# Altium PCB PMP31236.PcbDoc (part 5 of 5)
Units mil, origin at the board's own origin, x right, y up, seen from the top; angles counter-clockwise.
Board outline 6425 x 5322.16 mil, 6 copper layers (Top Layer, Power / GND 1, Signal Layer 1, Signal Layer 2, Power / GND 2, Bottom Layer), stack 78.712 mil thick; 732 components, 346 nets, 1735 pads, 719 vias.
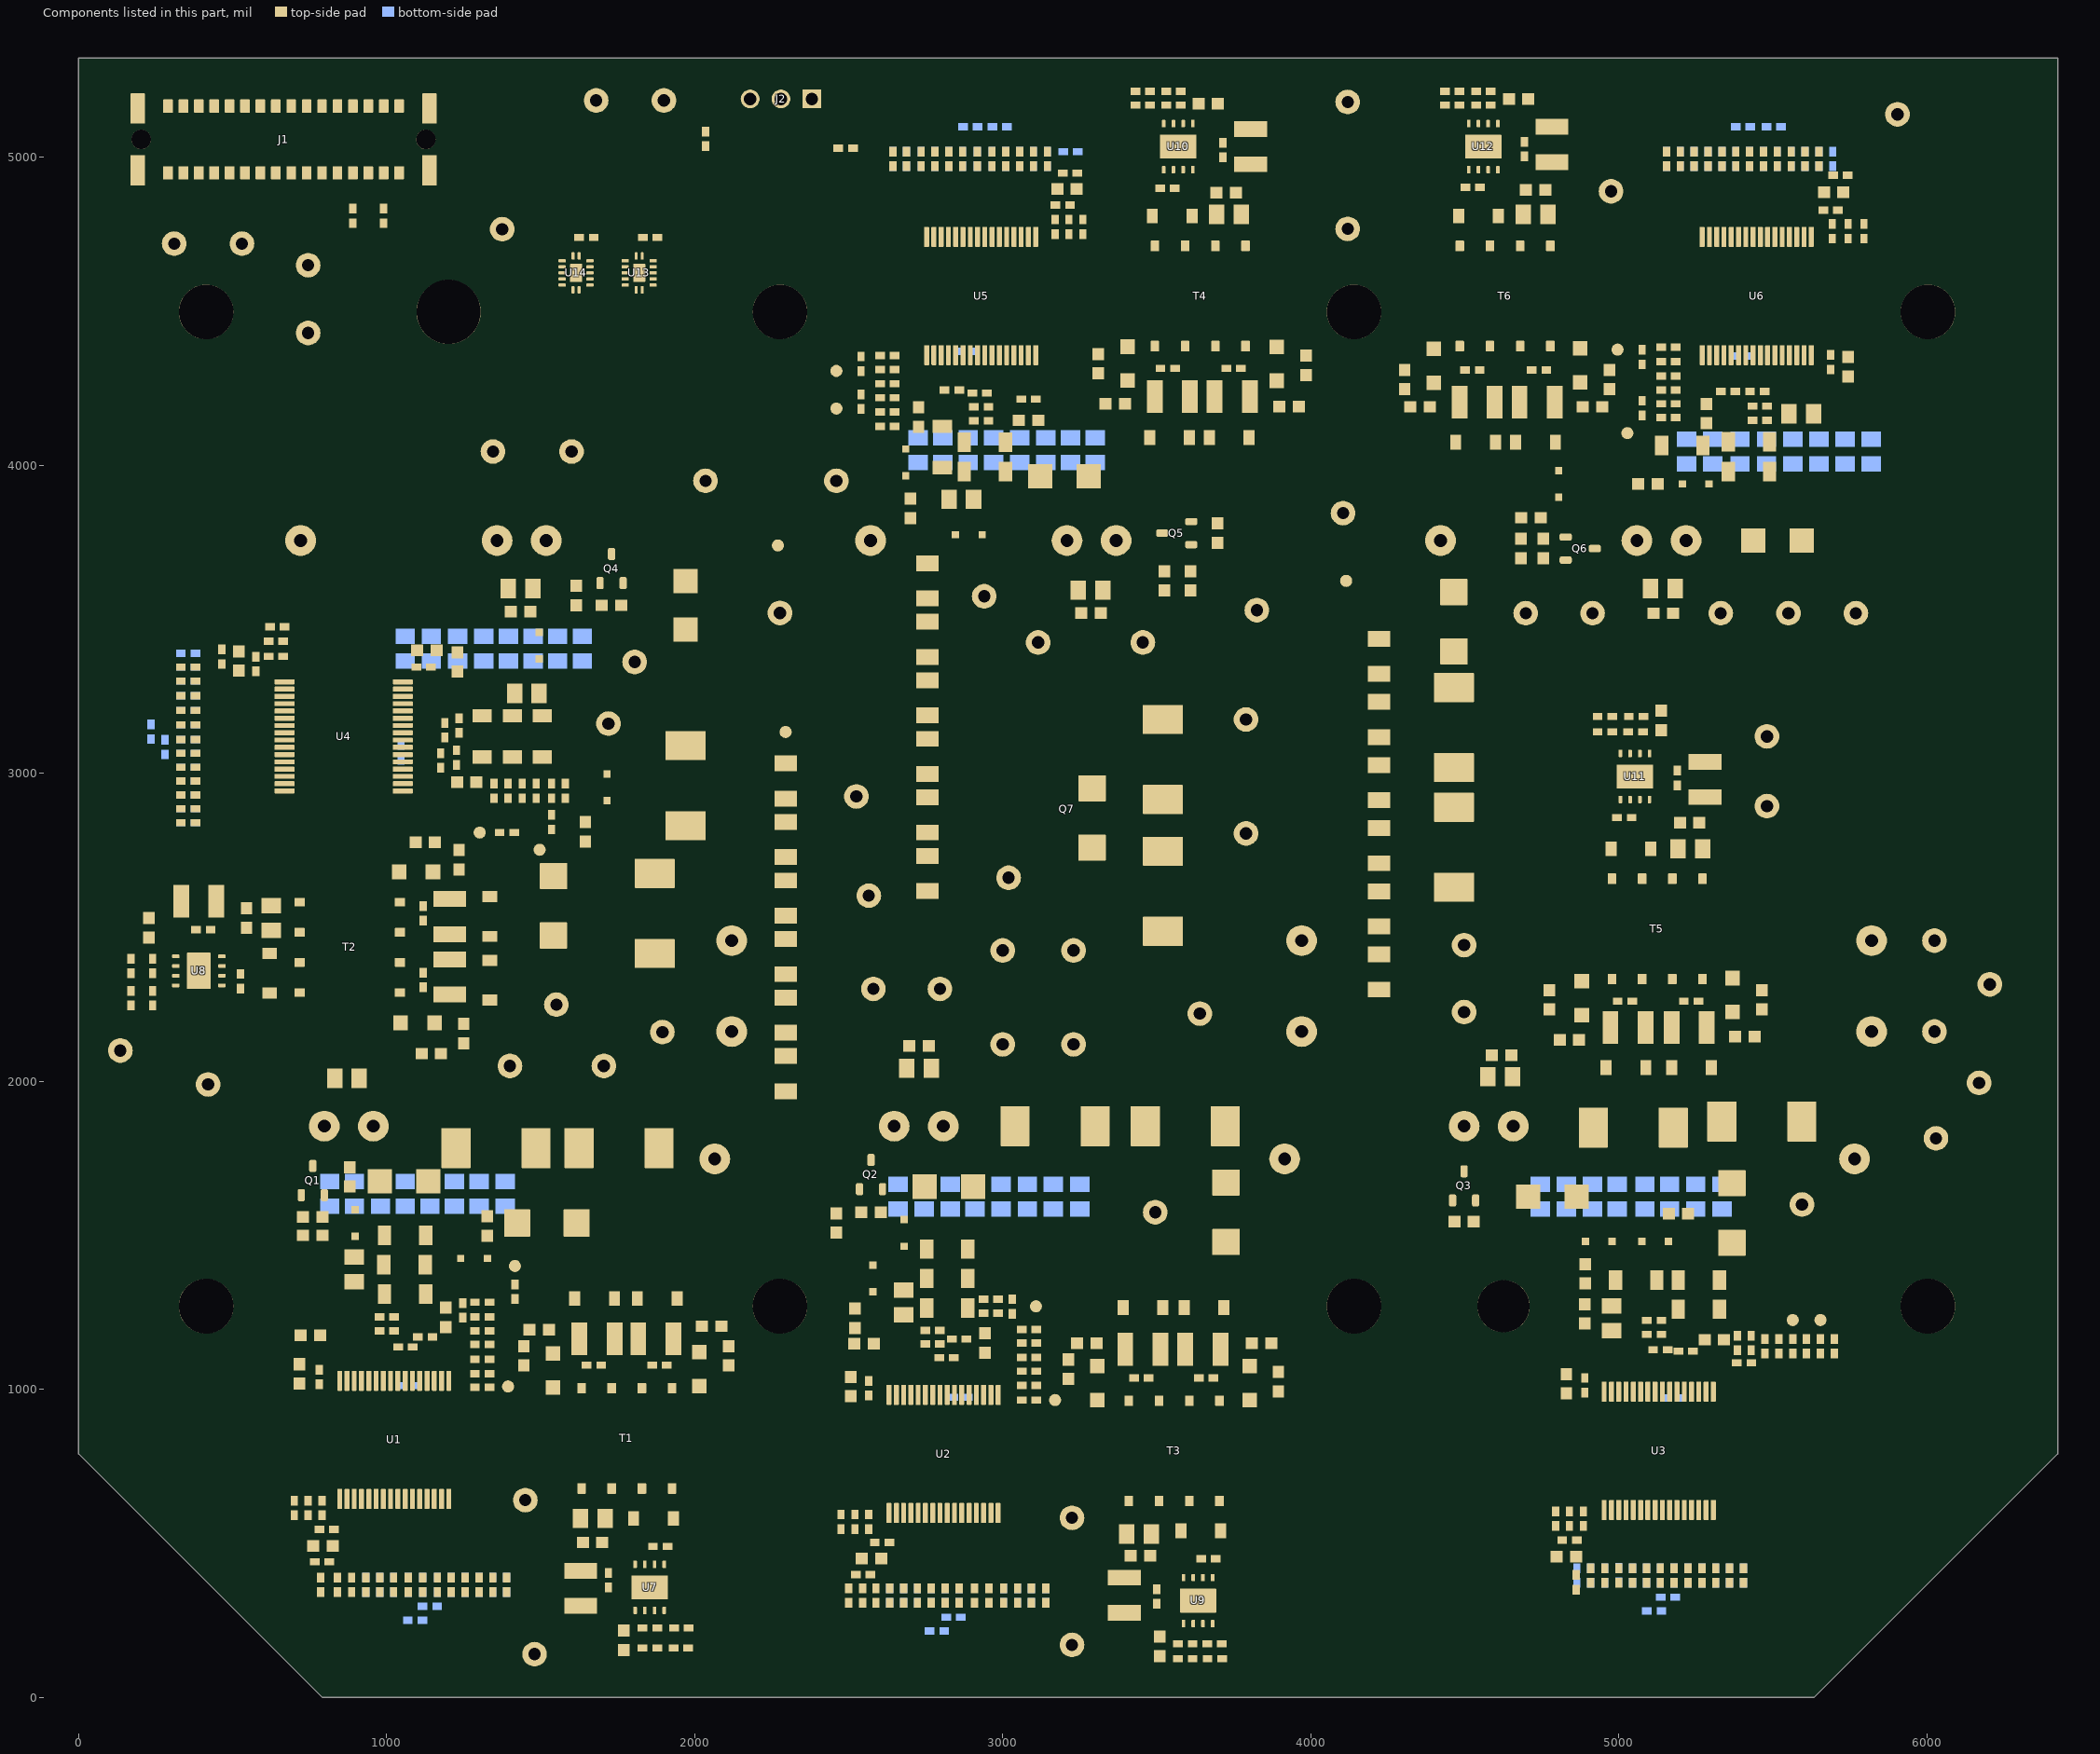
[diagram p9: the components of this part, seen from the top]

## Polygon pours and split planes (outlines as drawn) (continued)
VEE2H_W on Top Layer "VEE2H_W_L01_P120" (solid, pour order 120): 5047.32,1034.66 4992.95,1034.66 4898.39,1129.22 4898.39,1207.7 4950.93,1260.25 5103.1,1260.25 5122.32,1241.03 5122.32,1109.65
VCC2H_W on Top Layer "VCC2H_W_L01_P119" (solid, pour order 119): 4918.54,1270 4918.17,1270.38 4918.17,1485.26 4943.4,1510.5 5032.5,1510.5 5060.2,1482.8 5060.2,1288.32 5016.46,1244.57 4943.85,1244.57 4918.54,1269.88
VEE2H_W on Top Layer "VEE2H_W_L01_P118" (solid, pour order 118): 5283.54,1385.43 5300.61,1402.5 5392.5,1402.5 5410.35,1384.65 5410.35,1230.35 5403.62,1223.62 5294.59,1223.62 5283.54,1234.67
VCC2H_W on Top Layer "VCC2H_W_L01_P117" (solid, pour order 117): 5127.29,1106.81 5122.32,1111.78 5122.32,1190.43 5178.87,1190.43 5211.15,1158.15 5211.15,1101.93 5143.88,1034.66 5133.35,1057.94 5133.35,1076.24
VEE2H_W on Top Layer "VEE2H_W_L01_P099" (solid, pour order 99): 4925,1028.82 4925,1059.59 4871.78,1112.81 4773.27,1112.81 4760,1099.55 4760,1028.02 4772.86,1015.16 4911.34,1015.16
VSUP_PRIM on Top Layer "VSUP_PRIM_L01_P116" (solid, pour order 116): 2511.78,344.05 2511.8,344.07 2511.8,379.22 2519.32,386.73 2547.13,386.73 2547.13,410.35 2464.65,410.35 2450,395.71 2450,350.11 2463.01,337.1 2511.8,337.1
NetC31_1 on Top Layer "NETC31_1_L01_P115" (solid, pour order 115): 2547.13,410.35 2547.13,440.63 2678.31,571.81 2685,571.81 2685,466.66 2595.23,376.89 2547.13,376.89
GND on Top Layer "GND_L01_P114" (solid, pour order 114): 2565,431.2 2556.54,422.73 2499.4,422.73 2490,432.13 2490,476.08 2529.94,516.02 2606.72,516.02 2608.05,514.68 2608.05,485.87 2600.73,478.54 2571.45,478.54 2565,472.09
GND on Top Layer "GND_L01_P112" (solid, pour order 112): 3333.18,298.18 3188.27,153.27 3188.27,48.27 3833.27,48.27 3845,60 3845,321.37 3804.33,362.04 3333.18,362.04
GND on Top Layer "GND_L01_P111" (solid, pour order 111): 1554.91,333.21 1410,188.3 1410,105 1436.26,78.74 2028.74,78.74 2066.73,116.73 2066.73,378.1 2026.06,418.77 1554.91,418.77
VEE2H_U on Top Layer "VEE2H_U_L01_P110" (solid, pour order 110): 1201.63,1064.93 1246.68,1064.93 1246.68,988.26 1201.63,988.26
GND on Top Layer "GND_L01_P109" (solid, pour order 109): 5208.2,4770.22 5221.61,4783.62 5270.83,4783.62 5270.83,4704.82 5218.39,4704.82 5208.2,4715.01
GND on Top Layer "GND_L01_P108" (solid, pour order 108): 5622.98,4783.62 5682.71,4783.62 5704.01,4762.32 5704.01,4714.49 5692.63,4703.11 5622.98,4703.11
GND on Top Layer "GND_L01_P107" (solid, pour order 107): 848.05,677.95 788.32,677.95 767.02,656.65 767.02,608.82 778.4,597.44 848.05,597.44
GND on Top Layer "GND_L01_P106" (solid, pour order 106): 715.39,2942.83 715.39,2914.5 699.31,2898.42 649.88,2898.42 634.88,2913.42 634.88,2942.83
GND on Top Layer "GND_L01_P105" (solid, pour order 105): 1202.26,686.14 1230.6,686.14 1246.68,670.06 1246.68,620.63 1231.68,605.63 1202.26,605.63
GND on Top Layer "GND_L01_P104" (solid, pour order 104): 2985.22,637.32 3013.55,637.32 3029.63,621.24 3029.63,571.81 3014.63,556.81 2985.22,556.81
GND on Top Layer "GND_L01_P103" (solid, pour order 103): 2630.59,637.32 2570.87,637.32 2549.57,616.02 2549.57,568.19 2560.95,556.81 2630.59,556.81
GND on Top Layer "GND_L01_P102" (solid, pour order 102): 4952.83,650.51 4893.11,650.51 4871.81,629.21 4871.81,581.38 4883.19,570 4952.83,570
GND on Top Layer "GND_L01_P101" (solid, pour order 101): 5307.17,650.51 5335.5,650.51 5351.58,634.43 5351.58,585 5336.58,570 5307.17,570
VEE2H_W on Top Layer "VEE2H_W_L01_P100" (solid, pour order 100): 5307.17,1028.66 5328.19,1049.68 5374.97,1049.68 5390,1034.66 5390,965 5374.72,949.72 5307.17,949.72
NetC151_1 on Top Layer "NETC151_1_L01_P098" (solid, pour order 98): 5570.85,4765 5570.85,4854.79 5679.6,4963.54 5715.56,4963.54 5715.56,4925.86 5697.99,4908.3 5697.99,4827.15 5677.22,4806.38 5620.83,4806.38 5580.98,4766.54
GND on Top Layer "GND_L01_P097" (solid, pour order 97): 4892.09,3202.09 4925,3235 5500,3235 5555,3180 5555,3036.5 5455.21,2936.71 4942.84,2936.71 4942.84,2936.91 4892.09,2987.66
VSUP_GATE_BIAS on Top Layer "VSUP_GATE_BIAS_L01_P096" (solid, pour order 96): 3573.75,4972.39 3568.52,4967.16 3568.52,4890.72 3680.21,4890.72 3747.87,4823.06 3747.87,4687.01 3763.58,4671.31 3849.21,4671.31 3865,4687.1 3865,5030.38 3857.99,5037.39 3739.37,5037.39 3717.47,5015.48 3692.08,5015.48 3648.99,4972.39
VSUP_GATE_BIAS on Top Layer "VSUP_GATE_BIAS_L01_P095" (solid, pour order 95): 4563.99,4978.56 4558.76,4973.33 4558.76,4896.89 4670.45,4896.89 4738.11,4829.23 4738.11,4693.18 4753.82,4677.48 4839.44,4677.48 4855.24,4693.27 4855.24,5036.55 4848.23,5043.56 4729.61,5043.56 4707.7,5021.65 4682.32,5021.65 4639.22,4978.56
VSUP_GATE_BIAS on Top Layer "VSUP_GATE_BIAS_L01_P094" (solid, pour order 94): 5060.37,2933.62 5055.14,2928.39 5055.14,2851.95 5166.83,2851.95 5234.49,2784.29 5234.49,2648.24 5250.2,2632.53 5335.82,2632.53 5351.62,2648.33 5351.62,2991.61 5344.61,2998.62 5225.99,2998.62 5204.08,2976.71 5178.7,2976.71 5135.6,2933.62
VSUP_GATE_BIAS on Top Layer "VSUP_GATE_BIAS_L01_P093" (solid, pour order 93): 3626.25,372.77 3631.48,378 3631.48,454.44 3519.79,454.44 3452.13,522.1 3452.13,658.14 3436.42,673.85 3350.79,673.85 3335,658.06 3335,314.78 3342.01,307.77 3460.63,307.77 3482.53,329.67 3507.92,329.67 3551.01,372.77
VSUP_GATE_BIAS on Top Layer "VSUP_GATE_BIAS_L01_P092" (solid, pour order 92): 1846.16,417.77 1851.39,423 1851.39,499.44 1739.7,499.44 1672.03,567.1 1672.03,691.12 1653.15,710 1570,710 1554.91,694.91 1554.91,359.78 1561.92,352.77 1680.54,352.77 1702.44,374.67 1727.83,374.67 1770.92,417.77
VSUP_GATE_BIAS on Top Layer "VSUP_GATE_BIAS_L01_P091" (solid, pour order 91): 455,2363.75 460.23,2358.52 536.67,2358.52 536.67,2470.21 604.33,2537.87 740.37,2537.87 756.08,2553.58 756.08,2639.21 740.29,2655 397.01,2655 390,2647.99 390,2529.37 411.9,2507.47 411.9,2482.08 455,2438.99
NetD44_2 on Top Layer "NETD44_2_L01_P090" (solid, pour order 90): 713.48,2317.6 468.37,2317.6 468.37,2306.03 468.19,2305.84 525.06,2248.97 672.27,2248.97 721.9,2248.97 740.29,2267.36 740.29,2300.98 723.67,2317.6
NetD39_2 on Top Layer "NETD39_2_L01_P089" (solid, pour order 89): 1895.18,669.45 1895.18,424.34 1906.75,424.34 1906.94,424.16 1963.81,481.03 1963.81,628.24 1963.81,677.87 1945.42,696.26 1911.8,696.26 1895.18,679.64
NetD49_2 on Top Layer "NETD49_2_L01_P088" (solid, pour order 88): 3675.73,637.33 3675.73,392.22 3687.3,392.22 3687.49,392.04 3744.36,448.91 3744.36,596.12 3744.36,645.75 3725.97,664.14 3692.35,664.14 3675.73,647.52
NetD59_2 on Top Layer "NETD59_2_L01_P087" (solid, pour order 87): 5011.47,2661.63 5011.47,2906.74 4999.89,2906.74 4999.71,2906.93 4942.84,2850.06 4942.84,2702.84 4942.84,2653.21 4961.22,2634.83 4994.85,2634.83 5011.47,2651.45
NetD64_2 on Top Layer "NETD64_2_L01_P086" (solid, pour order 86): 4518.63,4718.24 4518.63,4963.36 4507.05,4963.36 4506.87,4963.54 4450,4906.67 4450,4759.45 4450,4709.83 4468.39,4691.44 4502.01,4691.44 4518.63,4708.06
NetD54_2 on Top Layer "NETD54_2_L01_P085" (solid, pour order 85): 3528.63,4713.42 3528.63,4958.53 3517.05,4958.53 3516.87,4958.71 3460,4901.84 3460,4754.63 3460,4705 3478.39,4686.61 3512.01,4686.61 3528.63,4703.23
GND on Top Layer "GND_L01_P084" (solid, pour order 84): 3107.17,4783.05 3183.6,4783.05 3188.08,4778.58 3188.08,4712.71 3174.97,4699.61 3107.17,4699.61
GND on Top Layer "GND_L01_P083" (solid, pour order 83): 2690.21,4765 2703.62,4778.41 2752.83,4778.41 2752.83,4699.61 2700.39,4699.61 2690.21,4709.79
GND on Top Layer "GND_L01_P082" (solid, pour order 82): 630.76,3400.5 693.89,3400.5 699.96,3394.43 699.96,3288.95 639.77,3288.95 630.76,3297.96
VCC2L_W on Top Layer "VCC2L_W_L01_P081" (solid, pour order 81): 5080.71,4105.43 5084.02,4102.11 5161.52,4102.11 5161.52,4021.52 5160,4020 5080,4020 5080.04,4020.04 5080.04,4105.14
GND2L_W on Top Layer "GND2L_W_L01_P080" (solid, pour order 80): 5257.17,3900.57 5257.17,3970.9 5111.57,4116.5 5111.57,4399.68 5157.68,4399.68 5167.48,4389.88 5457.73,4389.88 5457.73,3937.13 5421.18,3900.57
VEE2L_W on Top Layer "VEE2L_W_L01_P079" (solid, pour order 79): 5465.45,4221.87 5573.58,4330 5763.7,4330 5763.7,4329.84 5775.58,4317.97 5775.58,3950.58 5755,3930 5465.45,3930
VCC2L_W on Top Layer "VCC2L_W_L01_P078" (solid, pour order 78): 5605,4200 5699.11,4200 5706.61,4192.5 5706.61,4132.86 5690,4116.24 5605,4116.24
VCC2L_W on Top Layer "VCC2L_W_L01_P077" (solid, pour order 77): 5363.74,4251.81 5423.53,4311.59 5426.18,4311.59 5426.18,4290.49 5457.73,4258.94 5457.73,4180.69 5402.63,4180.69 5363.74,4219.57
GND2L_U on Top Layer "GND2L_U_L01_P076" (solid, pour order 76): 1163.19,3041.38 1257.38,3135.57 1665.06,3135.57 1730,3070.63 1730,2977.27 1702.71,2949.98 1233.21,2949.98 1163.19,3020
VCC2L_U on Top Layer "VCC2L_U_L01_P075" (solid, pour order 75): 1436.38,3153.28 1459.42,3176.32 1459.42,3380.85 1483.58,3405 1544.39,3405 1560,3389.39 1560,3166.75 1541.56,3148.31 1436.38,3148.31
VEE2L_U on Top Layer "VEE2L_U_L01_P074" (solid, pour order 74): 1447.24,3220 1447.24,3297.96 1414.2,3331 1232.15,3331 1201.46,3361.69 1201.46,3417.09 1187.95,3430.59 1141.89,3430.59 1127.02,3415.72 1127.02,3188.89 1162.63,3153.28 1419.99,3153.28 1447.24,3180.54
VCC2L_U on Top Layer "VCC2L_U_L01_P073" (solid, pour order 73): 1068.51,3099.88 1127.02,3041.38 1200.5,3041.38 1247,3087.88 1246.65,3088.22 1246.65,3155.43 1203.35,3155.43 1199.04,3151.12 1070,3151.12
VEE2H_V on Top Layer "VEE2H_V_L01_P070" (solid, pour order 70): 2725.37,1032.99 2616.22,1142.14 2616.22,1256.22 2625,1265 2701.78,1265 2721.47,1284.69 2721.47,1382.83 2738.5,1399.86 2777.89,1399.86 2794.55,1383.2 2794.55,1145.54 2731.18,1082.18 2731.18,1038.15
GND2H_U on Top Layer "GND2H_U_L01_P069" (solid, pour order 69): 1113.57,1105.87 1201.58,1193.87 1201.58,1233.62 1289.57,1233.62 1290,1233.19 1290,998.82 1299.84,988.98 1330.69,988.98 1386.47,1044.76 1386.47,1372.08 1202.26,1556.28 1028.98,1556.28 1008.35,1535.66 1008.35,1156.65 1059.14,1105.87
VCC2H_U on Top Layer "VCC2H_U_L01_P068" (solid, pour order 68): 854.55,1400 830,1424.55 830,1536.96 849.32,1556.28 1012.4,1556.28 1028.69,1540 1028.69,1400
VEE2H_U on Top Layer "VEE2H_U_L01_P067" (solid, pour order 67): 918.4,1090 1028.69,1183.75 1028.69,1424.01 1015.29,1437.4 954.96,1437.4 906.9,1389.34 844.34,1389.34 830,1375 830,1181.85
VEE2H_U on Top Layer "VEE2H_U_L01_P066" (solid, pour order 66): 688.39,1096.86 688.39,1135.65 700,1147.27 764.61,1147.27 817.56,1094.32 817.56,1054.98 802.58,1040 708.23,1040 688.39,1059.84
VCC2H_U on Top Layer "VCC2H_U_L01_P065" (solid, pour order 65): 1032.07,1147.25 1008.35,1170.96 1008.35,1197.94 1077.8,1197.94 1125,1150.74 1125,1125.32 1077.34,1077.65 1047.28,1077.65 1032.07,1092.86
VCC2H_V on Top Layer "VCC2H_V_L01_P064" (solid, pour order 64): 2710.5,1335.88 2710.5,1395.52 2734.98,1420 2785,1420 2785,1485.21 2775.21,1495 2661.23,1495 2625,1458.77 2625,1316.24 2650.48,1290.77 2710.53,1290.77
VEE2L_W on Top Layer "VEE2L_W_L01_P063" (solid, pour order 63): 5270.83,4323.37 5224.53,4323.37 5209.5,4338.4 5209.5,4384.06 5210.04,4384.06 5226.38,4400.39 5261.47,4400.39 5270.83,4391.04
GND2L_V on Top Layer "GND2L_V_L01_P062" (solid, pour order 62): 2652.8,3991.93 2782.48,3991.93 2830.91,3943.5 2941.81,3943.5 2941.81,4334.65 2891.07,4385.39 2575,4385.39 2575,4069.72
VEE2L_V on Top Layer "VEE2L_V_L01_P061" (solid, pour order 61): 2755,4390.39 2745,4400.39 2697.66,4400.39 2682.76,4385.48 2682.76,4338.1 2705.86,4315 2746.22,4315 2755,4323.78
VCC2L_V on Top Layer "VCC2L_V_L01_P060" (solid, pour order 60): 2881.77,3931.23 2844.74,3931.23 2835.91,3940.06 2835.91,4014.63 2826.13,4024.41 2759.88,4024.41 2750,4014.53 2750,3822.48 2816.38,3756.1 2871.19,3756.1 2881.77,3766.68
VCC2L_V on Top Layer "VCC2L_V_L01_P058" (solid, pour order 58): 2930,4188.19 2930,4284.98 2908.25,4306.73 2835,4233.48 2835,4213.7 2848.7,4200 2880.79,4200 2880.79,4184.74 2888.87,4176.65 2918.46,4176.65
VEE2L_V on Top Layer "VEE2L_V_L01_P057" (solid, pour order 57): 2930,4211.81 2939.84,4221.65 2940,4221.65 2940,4221.88 2984.77,4266.65 3083.54,4266.65 3083.54,3919.03 3021.93,3857.41 2879.36,3857.41 2865,3871.77 2865,3913.03 2930,3978.03
VEE2H_V on Top Layer "VEE2H_V_L01_P056" (solid, pour order 56): 2603.31,1011.89 2480.71,1011.89 2470,1022.6 2470,1087.76 2482.12,1099.88 2554.41,1099.88 2603.31,1050.98 2603.31,1014.99
VEE2H_V on Top Layer "VEE2H_V_L01_P055" (solid, pour order 55): 2985.22,1014.99 3035.79,1014.99 3035.79,944.93 2985.22,944.93
VCC2H_W on Top Layer "VCC2H_W_L01_P024" (solid, pour order 24): 5173.98,1992.5 5361,1992.5 5399,2030.5 5399,2254.5 5372.01,2281.5 5173.98,2281.5
VEE2H_W on Top Layer "VEE2H_W_L01_P023" (solid, pour order 23): 5077.83,1992.5 4890.81,1992.5 4852.81,2030.5 4852.81,2254.5 4879.8,2281.5 5077.83,2281.5
GND2H_W on Top Layer "GND2H_W_L01_P022" (solid, pour order 22): 5191.28,2355 5226.28,2320 5226.28,2044.8 5173.98,1992.5 5077.83,1992.5 5026.28,2044.06 5026.28,2325.94 5055.33,2355
VCC2L_U on Top Layer "VCC2L_U_L01_P021" (solid, pour order 21): 1382.5,2485.67 1382.5,2672.7 1344.5,2710.7 1120.5,2710.7 1093.5,2683.7 1093.5,2485.67
VEE2L_U on Top Layer "VEE2L_U_L01_P020" (solid, pour order 20): 1382.43,2389.16 1382.43,2202.13 1344.43,2164.13 1120.43,2164.13 1093.43,2191.13 1093.43,2389.16
VEE2H_V on Top Layer "VEE2H_V_L01_P019" (solid, pour order 19): 3603.81,1307.43 3790.84,1307.43 3828.84,1269.43 3828.84,1045.43 3801.84,1018.43 3603.81,1018.43
VEE2H_U on Top Layer "VEE2H_U_L01_P017" (solid, pour order 17): 1828.81,1342.43 2015.84,1342.43 2053.84,1304.43 2053.84,1080.43 2026.84,1053.43 1828.81,1053.43
VCC2H_U on Top Layer "VCC2H_U_L01_P016" (solid, pour order 16): 1731.94,1342.43 1544.91,1342.43 1506.91,1304.43 1506.91,1080.43 1533.9,1053.43 1731.94,1053.43
VCC2H_V on Top Layer "VCC2H_V_L01_P015" (solid, pour order 15): 3506.94,1307.43 3319.91,1307.43 3281.91,1269.43 3281.91,1045.43 3308.9,1018.43 3506.94,1018.43
VEE2L_V on Top Layer "VEE2L_V_L01_P014" (solid, pour order 14): 3595.74,4053.71 3408.71,4053.71 3370.71,4091.71 3370.71,4315.71 3397.7,4342.7 3595.74,4342.7
VCC2L_V on Top Layer "VCC2L_V_L01_P013" (solid, pour order 13): 3692.24,4053.64 3879.27,4053.64 3917.27,4091.64 3917.27,4315.64 3890.28,4342.63 3692.24,4342.63
VCC2L_W on Top Layer "VCC2L_W_L01_P012" (solid, pour order 12): 4680.67,4042.5 4867.7,4042.5 4905.7,4080.5 4905.7,4304.5 4878.7,4331.5 4680.67,4331.5
VEE2L_W on Top Layer "VEE2L_W_L01_P011" (solid, pour order 11): 4584.53,4042.5 4397.5,4042.5 4359.5,4080.5 4359.5,4304.5 4386.5,4331.5 4584.53,4331.5
NetC196_2 on Top Layer "NETC196_2_L01_P010" (solid, pour order 10): 660,2514.91 660,2385.09 650,2375.09 649.97,2375.11 596.49,2375.11 585,2386.6 585,2452.04 571.42,2465.62 571.36,2465.56 529.71,2465.56 515.67,2479.59 515.67,2514.91 526.38,2525.62 649.29,2525.62
NetC216_2 on Top Layer "NETC216_2_L01_P009" (solid, pour order 9): 3709.08,4773.05 3579.26,4773.05 3569.26,4783.05 3569.29,4783.08 3569.29,4836.56 3580.78,4848.05 3646.21,4848.05 3659.79,4861.63 3659.73,4861.69 3659.73,4903.34 3673.77,4917.38 3709.08,4917.38 3719.79,4906.67 3719.79,4783.76
NetC236_2 on Top Layer "NETC236_2_L01_P008" (solid, pour order 8): 4714.12,4773.62 4584.3,4773.62 4574.3,4783.62 4574.33,4783.65 4574.33,4837.13 4585.82,4848.62 4651.25,4848.62 4664.83,4862.21 4664.77,4862.26 4664.77,4903.92 4678.81,4917.95 4714.12,4917.95 4724.83,4907.24 4724.83,4784.33
NetC226_2 on Top Layer "NETC226_2_L01_P007" (solid, pour order 7): 5214.91,2720 5085.09,2720 5075.09,2730 5075.11,2730.03 5075.11,2783.51 5086.6,2795 5152.04,2795 5165.62,2808.58 5165.56,2808.64 5165.56,2850.29 5179.59,2864.33 5214.91,2864.33 5225.62,2853.62 5225.62,2730.71
NetC206_2 on Top Layer "NETC206_2_L01_P006" (solid, pour order 6): 3465.09,575 3594.91,575 3604.91,565 3604.89,564.97 3604.89,511.49 3593.4,500 3527.96,500 3514.38,486.42 3514.44,486.36 3514.44,444.71 3500.41,430.67 3465.09,430.67 3454.38,441.38 3454.38,564.29
NetC186_2 on Top Layer "NETC186_2_L01_P005" (solid, pour order 5): 1685.18,620 1815,620 1825,610 1824.97,609.97 1824.97,556.49 1813.48,545 1748.05,545 1734.47,531.42 1734.53,531.36 1734.53,489.71 1720.5,475.67 1685.18,475.67 1674.47,486.38 1674.47,609.29
GND2L_U on Top Layer "GND2L_U_L01_P004" (solid, pour order 4): 1020,2502.97 1055,2537.97 1330.2,2537.97 1382.5,2485.67 1382.5,2389.53 1330.94,2337.97 1049.06,2337.97 1020,2367.03
GND2L_W on Top Layer "GND2L_W_L01_P003" (solid, pour order 3): 4697.97,4405 4732.97,4370 4732.97,4094.8 4680.67,4042.5 4584.53,4042.5 4532.97,4094.06 4532.97,4375.94 4562.03,4405
GND2L_V on Top Layer "GND2L_V_L01_P002" (solid, pour order 2): 3709.55,4416.14 3744.55,4381.14 3744.55,4105.94 3692.24,4053.64 3596.1,4053.64 3544.55,4105.19 3544.55,4387.08 3573.6,4416.14
GND2H_U on Top Layer "GND2H_U_L01_P001" (solid, pour order 1): 1715,980 1680,1015 1680,1290.2 1732.3,1342.5 1828.44,1342.5 1880,1290.94 1880,1009.06 1850.94,980
GND2H_V on Top Layer "GND2H_V_L01_P000" (solid, pour order 0): 3490,945 3455,980 3455,1255.2 3507.3,1307.5 3603.44,1307.5 3655,1255.94 3655,974.06 3625.94,945
GND on Bottom Layer "GND_L06_P162" (solid, pour order 162): 54 vertices, not listed, extent -90.16,4.81 6324.84,5314.81
Vg_LS_W on Bottom Layer "VG_LS_W_L06_P054" (solid, pour order 54): 5180,4030 5180,3740 5205,3715 5655,3715 5860,3920 5860,4030
NetR209_1 on Bottom Layer "NETR209_1_L06_P053" (solid, pour order 53): 5343.66,4054.94 5343.66,4151.09 5480,4287.43 5480,4295.08 5470,4305.08 5315.08,4305.08 5180,4170 5180,4054.94
NetR221_1 on Bottom Layer "NETR221_1_L06_P052" (solid, pour order 52): 5583.31,4290.19 5583.31,4166.69 5695.06,4054.94 5860,4054.94 5860,4177.54 5732.46,4305.08 5593.11,4305.08
NetR218_1 on Bottom Layer "NETR218_1_L06_P051" (solid, pour order 51): 5525,4055 5525,4280.25 5544.89,4300.13 5560.96,4300.13 5560.96,4294.04 5685,4170 5684.94,4169.94 5684.94,4054.94
NetR212_1 on Bottom Layer "NETR212_1_L06_P050" (solid, pour order 50): 5517.29,4294.98 5517.29,4055 5360,4055 5360,4154.63 5500.19,4294.82
Vg_LS_V on Bottom Layer "VG_LS_V_L06_P049" (solid, pour order 49): 2685,4035 2685,3930 2805,3810 3245,3810 3350,3705 3405,3705 3440,3740 3440,3929.21 3334.21,4035
NetR178_1 on Bottom Layer "NETR178_1_L06_P048" (solid, pour order 48): 3061.89,4296.44 3061.89,4183.11 3180,4065 3340,4065 3340,4150 3180.06,4309.94 3159.94,4309.94 3075.39,4309.94
NetR175_1 on Bottom Layer "NETR175_1_L06_P047" (solid, pour order 47): 3019.68,4290.34 3029.34,4300 3044.15,4300 3173.39,4170.76 3173.39,4065 3019.68,4065
NetR166_1 on Bottom Layer "NETR166_1_L06_P046" (solid, pour order 46): 2685,4065 2685,4160.71 2840,4315.71 2944.64,4315.71 2960.35,4300 2845,4184.65 2845,4065
NetR169_1 on Bottom Layer "NETR169_1_L06_P045" (solid, pour order 45): 2850,4065 2850,4173.32 2978.2,4301.53 2997.02,4301.53 3005,4289.8 3005,4065
NetR123_1 on Bottom Layer "NETR123_1_L06_P044" (solid, pour order 44): 1119.85,3157.24 1277.24,3157.24 1515,3395 1675,3395 1675,3130 1580,3035 1207.5,3035 1106.93,3135.57 1106.93,3145
NetR126_1 on Bottom Layer "NETR126_1_L06_P043" (solid, pour order 43): 1118.5,3190 1323.5,3395 1507.79,3395 1507.79,3217.79 1447.24,3157.24 1119.85,3157.24
Vg_LS_U on Bottom Layer "VG_LS_U_L06_P042" (solid, pour order 42): 1020,3415 1020,3506.5 1198.5,3685 1380,3685 1500,3805 1545,3805 1670,3680 1670,3415
NetR132_1 on Bottom Layer "NETR132_1_L06_P041" (solid, pour order 41): 1118.5,3235 1191.02,3307.52 1191.02,3395 1348.88,3395 1348.88,3308.88 1255,3215 1116.47,3215
NetR135_1 on Bottom Layer "NETR135_1_L06_P040" (solid, pour order 40): 1094.18,3250.82 1020,3325 1020,3395 1182.01,3395 1182.01,3312.01 1120.82,3250.82
NetR88_1 on Bottom Layer "NETR88_1_L06_P037" (solid, pour order 37): 5060.2,1065 5208.78,1068.59 5208.78,1613.47 5045.8,1613.47 5045.8,1261.9 5060.2,1247.5
NetR92_1 on Bottom Layer "NETR92_1_L06_P038" (solid, pour order 38): 5015,1065.53 5015,1066.8 4871.81,1210 4871.81,1613.47 4975,1613.47 5034.87,1553.6 5034.87,1059.57 5015.44,1059.57
NetR96_1 on Bottom Layer "NETR96_1_L06_P039" (solid, pour order 39): 4984.01,1054.69 4850.31,1054.69 4705,1200 4705,1614.23 4804.23,1614.23 4990.78,1427.69 4990.78,1061.46
NetR85_1 on Bottom Layer "NETR85_1_L06_P036" (solid, pour order 36): 5102.8,1097.48 5208.78,1203.46 5208.78,1615 5370,1615 5372.01,1612.99 5372.01,1192.01 5235,1055 5102.8,1055
Vg_HS_W on Bottom Layer "VG_HS_W_L06_P035" (solid, pour order 35): 4510,1630 4405,1735 4405,1880 4445,1920 4535,1920 4640,1815 5320,1815 5370,1765 5370,1630
NetR20_1 on Bottom Layer "NETR20_1_L06_P034" (solid, pour order 34): 875.93,1090 940,1154.07 940,1620 775,1620 715,1560 715,1218.67 854.04,1079.63 874.81,1079.63 874.81,1088.44 885,1098.63
NetR54_1 on Bottom Layer "NETR54_1_L06_P028" (solid, pour order 28): 2715.1,1034.9 2734.98,1054.78 2734.98,1144.98 2950,1360 2950,1610 2790,1610 2790.35,1609.65 2790.35,1515.35 2638.13,1363.13 2638.13,1086.51 2689.74,1034.9
NetR50_1 on Bottom Layer "NETR50_1_L06_P027" (solid, pour order 27): 2955,1610 2955,1394.43 2734.98,1174.4 2734.98,1035.03 2765.11,1035.03 3120,1396.33 3120,1610
NetR16_1 on Bottom Layer "NETR16_1_L06_P033" (solid, pour order 33): 926.8,1090 926.8,1090.66 951.46,1115.33 951.46,1196.1 1105.92,1350.56 1106.5,1351.14 1106.5,1620 951.46,1620 951.46,1506.04 885,1439.58 885,1115 910,1090
NetR12_1 on Bottom Layer "NETR12_1_L06_P032" (solid, pour order 32): 1105,1620 1260,1620 1260,1364.6 980,1084.6 956.69,1084.6 956.69,1203.17 1105,1351.48
NetR9_1 on Bottom Layer "NETR9_1_L06_P031" (solid, pour order 31): 1265,1365 1000,1100 1000,1088.78 1008.35,1080.43 1175.43,1080.43 1425,1330 1425,1620 1265,1620
Vg_HS_U on Bottom Layer "VG_HS_U_L06_P030" (solid, pour order 30): 1410.46,1639.69 1425,1654.23 1425,1755 1370,1810 925,1810 830,1905 760,1905 735,1880 735,1689.95 782.22,1642.73
NetR58_1 on Bottom Layer "NETR58_1_L06_P029" (solid, pour order 29): 2609.98,1030.02 2490,1150 2490,1501.75 2598.25,1610 2785,1610 2785,1143.96 2671.06,1030.02
NetR47_1 on Bottom Layer "NETR47_1_L06_P026" (solid, pour order 26): 3130,1610 3130,1399.86 2777.81,1047.67 2777.81,1030.02 3037.02,1030.02 3288.66,1281.66 3288.66,1610
Vg_HS_V on Bottom Layer "VG_HS_V_L06_P025" (solid, pour order 25): 2640,1625 2585,1680 2585,1875 2625,1915 2685,1915 2795,1805 3270.41,1805 3295.41,1780 3295.41,1648.5 3271.91,1625
GND on Power / GND 1 "GND_L02_P113" (solid, pour order 113): 54 vertices, not listed, extent -90,5 6325,5315
VEE2L_W on Power / GND 1 "VEE2L_W_L02_P147" (solid, pour order 147): 5749.6,3935.33 5649.59,3835.31 4408.67,3835.31 4311.08,3932.9 4311.08,4273.7 4438.08,4400.71 5665.69,4400.71 5749.6,4316.79
VEE2L_U on Power / GND 1 "VEE2L_U_L02_P145" (solid, pour order 145): 1379.35,2160 1480.59,2261.24 1480.59,3301.09 1419.99,3361.69 1053.54,3361.69 1012.4,3320.55 1012.4,2214.43 1066.83,2160
VEE2L_V on Power / GND 1 "VEE2L_V_L02_P133" (solid, pour order 133): 2575.79,4328.48 2647.7,4400.39 3859.58,4400.39 3930,4329.97 3930,4016.23 3762.73,3848.96 2745.61,3848.96 2575.79,4018.78
VEE2H_U on Power / GND 1 "VEE2H_U_L02_P131" (solid, pour order 131): 1012.4,993.9 1013.03,994.53 1987.49,994.53 2046.4,1053.43 2046.4,1301.03 1965.26,1382.17 771.97,1382.17 700,1310.19 700,1055.4 760.87,994.53
VEE2H_W on Power / GND 1 "VEE2H_W_L02_P130" (solid, pour order 130): 4730,1004.72 4785,949.72 5385.07,949.72 5502.41,1067.07 5502.41,2169.09 5371.5,2300 4860,2300 4730,2170
VEE2H_V on Power / GND 1 "VEE2H_V_L02_P126" (solid, pour order 126): 3793.33,1303.32 2995.27,1303.32 2811.36,1487.23 2629.27,1487.23 2480.71,1338.67 2480.71,1048.66 2584.37,945 3789.84,945 3828.84,984 3828.84,1267.81
VSUP_GATE_BIAS on Power / GND 2 "VSUP_GATE_BIAS_L05_P164" (solid, pour order 164): 54 vertices, not listed, extent -89.82,4.86 6325.18,5314.86
GND2L_V on Power / GND 2 "GND2L_V_L05_P148" (solid, pour order 148): 2578.16,4329.53 2650.07,4401.45 3861.95,4401.45 3975,4288.4 3975,3975 3695,3695 2902.99,3695 2578.16,4019.83
GND2L_W on Power / GND 2 "GND2L_W_L05_P134" (solid, pour order 134): 5748.52,3935.01 5500.71,3687.2 4555.39,3687.2 4310,3932.59 4310,4273.39 4437,4400.39 5664.61,4400.39 5748.52,4316.48
GND2L_U on Power / GND 2 "GND2L_U_L05_P132" (solid, pour order 132): 1422.19,2330 1665.06,2572.87 1665.06,3674.94 1535,3805 1252.02,3805 1012.4,3565.38 1012.4,2395.18 1077.58,2330
GND2H_W on Power / GND 2 "GND 2-GND2H_W" (solid, pour order 140): 4630,2500 4760.6,2369.4 5300.93,2370.57 5502.41,2169.09 5502.41,1067.07 5385.07,949.72 4785,949.72 4730,1004.72 4730,1410 4435,1705 4435,2476.89 4458.11,2500
GND2H_U on Power / GND 2 "GND2H_U_L05_P136" (solid, pour order 136): 2046.4,1119.57 2046.4,1301.03 1965.26,1382.17 1502.72,1382.17 992.39,1892.5 791.69,1892.5 694.19,1795 694.19,1157.2 857.5,993.9 858.13,994.53 1903.49,994.53
GND2H_V on Power / GND 2 "GND2H_V_L05_P128" (solid, pour order 128): 3828.84,1731 3654.84,1905 2615,1905 2565,1855 2565,1088.05 2708.05,945 3789.84,945 3828.84,984
VCC2L_U on Signal Layer 1 "VCC2L_U_L03_P144" (solid, pour order 144): 1457.86,2553.58 1535,2630.72 1535,3318.5 1491.81,3361.69 1053.54,3361.69 1012.4,3320.55 1012.4,2598.14 1056.96,2553.58
VCC2L_V on Signal Layer 1 "VCC2L_V_L03_P143" (solid, pour order 143): 3932.2,3934.62 3782.58,3785 2775.61,3785 2733.04,3827.57 2733.04,4299.04 2833.99,4400 3848.28,4400 3932.2,4316.08
VCC2L_W on Signal Layer 1 "VCC2L_W_L03_P141" (solid, pour order 141): 5748.52,3935.01 5648.5,3835 4829,3835 4738.11,3925.89 4738.11,4311.81 4826.69,4400.39 5664.61,4400.39 5748.52,4316.48
VCC2H_W on Signal Layer 1 "VCC2H_W_L03_P137" (solid, pour order 137): 4730,1004.72 4785,949.72 5385.07,949.72 5502.41,1067.07 5502.41,2169.09 5371.5,2300 4860,2300 4730,2170
VCC2H_U on Signal Layer 1 "VCC2H_U_L03_P135" (solid, pour order 135): 1570.54,1365 1172.2,1365 976.2,1561 863.86,1561 764.71,1461.85 764.71,1126.95 897.76,993.9 1579.97,993.9 1654.77,1068.7 1654.77,1280.76
VCC2H_V on Signal Layer 1 "VCC2H_V_L03_P127" (solid, pour order 127): 3392.13,1302.72 2993.8,1302.72 2809.89,1486.62 2627.8,1486.62 2563.53,1422.35 2563.53,1087.45 2696.58,954.4 3378.79,954.4 3453.59,1029.2 3453.59,1241.26

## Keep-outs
Keep-Out Layer:
  text ".Layer_Name" at 577,-858.49 h30

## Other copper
Top Layer:
  pour cut-out: 599.51,3522.19 486.43,3635.27 486.43,3897.05 488.37,3897.05 578.37,3987.05 858.72,3987.05 858.72,3521.58
  text ".Layer_Name" at 577,-858.49 h30
Power / GND 1:
  pour cut-out: 599.51,3522.19 486.43,3635.27 486.43,3897.05 488.37,3897.05 578.37,3987.05 858.72,3987.05 858.72,3521.58
Power / GND 2:
  pour cut-out: 599.51,3522.19 486.43,3635.27 486.43,3897.05 488.37,3897.05 578.37,3987.05 858.72,3987.05 858.72,3521.58
Bottom Layer:
  pour cut-out: 599.51,3522.19 486.43,3635.27 486.43,3897.05 488.37,3897.05 578.37,3987.05 858.72,3987.05 858.72,3521.58
  text ".Layer_Name" at 577,-858.49 h30

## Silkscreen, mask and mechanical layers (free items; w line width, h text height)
Top Overlay:
  text ".Layer_Name" at 577,-858.49 h30
Bottom Overlay:
  text ".Layer_Name" at 577,-858.49 h30
Top Paste:
  text ".Layer_Name" at 577,-858.49 h30
Bottom Paste:
  text ".Layer_Name" at 577,-858.49 h30
Top Solder:
  text ".Layer_Name" at 577,-858.49 h30
  text ".Layer_Name" at 577,-858.49 h30
Bottom Solder:
  text ".Layer_Name" at 577,-858.49 h30
Drill Guide:
  text ".Layer_Name" at 577,-858.49 h30
M1 Board Outline:
  the board outline again, w10
  text ".Layer_Name" at 577,-858.49 h30
M2 Board Dimensions:
  rectangle: 125,-400 500,-275
  rectangle: 0,-275 125,-150
  lines w7: 0,-275 1000,-275 ; 125,-400 125,-150 ; 250,-400 250,-150 ; 500,-400 500,-150 ; 750,-400 750,-150 ; 0,-400 0,-150 1000,-150 1000,-400 0,-400
  text ".Layer_Name" at 577,-858.49 h30
M3 3D STEP Top:
  text ".Layer_Name" at 577,-858.49 h30
M4 3D STEP Bottom:
  text ".Layer_Name" at 577,-858.49 h30
M5 Assembly Top:
  lines w10: -292,-930.17 6308,-930.17 ; -292,-726.83 6310,-726.83 ; -292,-523.5 -292,-1133.5 3713,-1133.5 6310,-1133.5 6310,-523.5 -291.5,-523.5 -291.5,-1133.5 1284,-1133.5 ; 2173,-1133.5 2173,-523.5 ; 3440,-726.83 3440,-523.5 ; 4280,-726.83 4280,-523.5 ; 4902,-1140 4902,-937.17
  text "COMPONENTS MARKED 'DNP' SHOULD NOT BE POPULATED." at 1153.5,-318.5 h30
  text "ASSEMBLY VARIANT:" at 1153,-434 h30
  text ".VariantName" at 2189,-434 h30
  text "PCB VIEWED FROM TOP SIDE" at -228.5,-655.67 h30
  text "BOARD #:" at 2248,-655.67 h30
  text ".PRJ_Number" at 2793.5,-655.67 h30
  text "REV:" at 3638,-655.67 h30
  text ".PCB_Rev" at 3929.5,-655.67 h30
  text "SVN REV:" at 4476,-655.67 h30
  text ".VersionControl_RevNumber" at 4982,-655.67 h30
  text "TID #:" at 2248,-859 h30
  text ".TID" at 2793.5,-859 h30
  text "PLOT NAME =" at -228.5,-1064.34 h30
  text ".plot_File_Name" at 577,-1064.34 h30
  text "GENERATED    :" at 2250,-1064.34 h30
  text ".Print_Date" at 3119.5,-1064.34 h30
  text ".Print_Time" at 3848.5,-1064.34 h30
  text "TEXAS INSTRUMENTS" at 5113,-1064.34 h30
M6 Assembly Bottom:
  lines w10: -292.5,-727.33 6309.5,-727.33 ; -290.5,-930.67 6309.5,-930.67 ; 1115.5,-1140.5 1115.5,-937.67 ; 1737.5,-727.33 1737.5,-524 ; 2577.5,-727.33 2577.5,-524 ; 3844.5,-1134 3844.5,-524 ; 4733.5,-1134 6309,-1134 6309,-524 -292.5,-524 -292.5,-1134 2304.5,-1134 6309.5,-1134 6309.5,-524
  text "COMPONENTS MARKED 'DNP' SHOULD NOT BE POPULATED." at 6102,-318 h30
  text ".VariantName" at 5058,-434 h30
  text "ASSEMBLY VARIANT:" at 6097,-434 h30
  text ".VersionControl_RevNumber" at 1035.5,-656.17 h30
  text "SVN REV:" at 1541.5,-656.17 h30
  text ".PCB_Rev" at 2088,-656.17 h30
  text "REV:" at 2379.5,-656.17 h30
  text ".PRJ_Number" at 3224,-656.17 h30
  text "BOARD #:" at 3769.5,-656.17 h30
  text "PCB VIEWED FROM BOTTOM SIDE" at 6246,-656.17 h30
  text ".TID" at 3224,-859.5 h30
  text "TID #:" at 3769.5,-859.5 h30
  text "TEXAS INSTRUMENTS" at 904.5,-1064.84 h30
  text ".Print_Time" at 2169,-1064.84 h30
  text ".Print_Date" at 2898,-1064.84 h30
  text "GENERATED    :" at 3767.5,-1064.84 h30
  text ".plot_File_Name" at 5440.5,-1064.84 h30
  text "PLOT NAME =" at 6246,-1064.84 h30
M9 Title Sheet:
  drawing of 57 lines, arcs and shapes, not listed
  text "1" at 739.84,8036.5 h70
  text "2" at 3235.5,8036.5 h70
  text "3" at 5724.84,8036.5 h70
  text "4" at 8231.51,8036.5 h70
  text "5" at 10730.5,8036.5 h70
  text "6" at 13235.5,8036.5 h70
  text "A" at -416.5,6893.5 h70
  text "A" at 14383.5,6893.5 h70
  text "B" at -416.5,4513.5 h70
  text "B" at 14383.5,4513.5 h70
  text "C" at -416.5,2138.5 h70
  text "C" at 14383.5,2138.5 h70
  text "PROJECT TITLE:" at 11343.5,277.5 h45
  text ".PRJ_Title" at 11393.5,144.17 h70
  text "DESIGNED FOR:" at 11343.5,-23.5 h45
  text ".PRJ_Customer" at 11393.5,-163.5 h70
  text "D" at -416.5,-231.5 h70
  text "D" at 14383.5,-231.5 h70
  text "FILE NAME:" at 11343.5,-323.5 h45
  text ".PCB_File_Name_No_Path" at 11393.5,-443.5 h70
  text "Texas Instruments (TI) and/or its licensors do not warrant the accuracy or completeness of this specification" at 6374,-605.34 h45
  text "ENGINEER:" at 11343.5,-613.5 h45
  text "LAYOUT BY:" at 12848.5,-613.5 h45
  text "or any information contained therein. TI and/or its licensors do not warrant that this design will meet" at 6329.01,-718 h45
  text ".PRJ_Engineer" at 11393.5,-768.49 h70
  text ".PCB_Layout" at 12899,-768.49 h70
  text "the specifications, will be suitable for your application or fit for any particular purpose, or will operate in" at 6329.01,-830.67 h45
  text ".Layer_Name" at 577,-858.49 h30
  text "ALTIUM DESIGNER VERSION:" at 12848.5,-923.5 h45
  text "an implementation. TI and/or its licensors do not warrant that the design is production worthy. You should" at 6329.01,-943.33 h45
  text "completely validate and test your design implementation to confirm the system functionality for your application." at 6374,-1056 h45
  text ".print_Scale" at 11393.5,-1056.83 h70
  text ".Application_BuildNumber" at 12899,-1056.83 h70
  text "1" at 739.84,-1263.5 h70
  text "2" at 3235.5,-1263.5 h70
  text "3" at 5724.84,-1263.5 h70
  text "4" at 8231.51,-1263.5 h70
  text "5" at 10730.5,-1263.5 h70
  text "6" at 13235.5,-1263.5 h70
M10 Fab Notes:
  drawing of 173 lines, arcs and shapes, not listed
  text "DESIGN INFORMATION" at 12377.02,6201 h30
  text "MIN. TRACK WIDTH:" at 11732.46,6021 h30
  text "8" at 12828.7,6021 h30
  text "MIL" at 12983.46,6021 h30
  text "MIN. CLEARANCE:" at 11732.46,5889 h30
  text "0.2" at 12768.7,5889 h30
  text "mm" at 12983.46,5889 h30
  text "MIN. VIA PAD SIZE:" at 11732.46,5757 h30
  text "24" at 12798.71,5757 h30
  text "MIL" at 12983.46,5757 h30
  text "0.05mm (2MIL)" at 12427.46,5615.29 h30
  text "MINIMUM ANNULAR RING" at 11403.23,5611 h30
  text "EXTERNAL" at 13135.46,5611 h30
  text "PER" at 11603.23,5493 h30
  text "IPC-D-275 CLASS 2 LEVEL C" at 11823.23,5493 h30
  text "MIL, HOLES" at 13311.46,5380.71 h30
  text "+/-" at 12919,5380 h30
  text "+/-" at 13773,5380 h30
  text "REGISTRATION TOLERANCES:" at 11403.23,5375 h30
  text "METAL" at 12603,5375 h30
  text "5" at 13179.2,5375 h30
  text "3" at 14012.2,5375 h30
  text "MIL" at 14128.46,5375 h30
  text "+/-" at 13773,5262 h30
  text "HOLE SIZE TOLERANCE (UNLESS OTHERWISE SPECIFIED):" at 11403.23,5257 h30
  text "3" at 14012.2,5257 h30
  text "MIL" at 14128.46,5257 h30
  text "MATERIAL:" at 11328.46,5047.54 h30
  text "FR-4 High Tg" at 12314.9,4907.21 h30
  text "FR-408" at 11749.46,4898.64 h30
  text "OTHER" at 13237.46,4898.64 h30
  text "X" at 12160,4895 h30
  text "62 MIL (1.6mm) +/-10%" at 12069.56,4735.92 h30
  text "THICKNESS:" at 11403.23,4731.64 h30
  text "X" at 11941.4,4731.64 h30
  text "OTHER" at 13354.46,4731.64 h30
  text "TOLERANCE:" at 11403.23,4573.64 h30
  text "X" at 12242.53,4573.64 h30
  text "ANSI IPC-6012 TYPE 3 CLASS 2" at 12429.48,4573.64 h30
  text "OTHER +/-" at 12429.46,4417.64 h30
  text "BOW & TWIST:" at 11403.23,4260.64 h30
  text "X" at 12242.53,4260.64 h30
  text "ANSI IPC-6012 TYPE 3 CLASS 2" at 12429.48,4260.64 h30
  text "OTHER +/-" at 12429.46,4102.13 h30
  text "DRILLING:" at 11328.46,3963.64 h30
  text "REFERENCE:" at 11403.23,3846.64 h30
  text "X" at 12051.46,3846.64 h30
  text "AS SHOWN" at 12238.46,3846.64 h30
  text "X" at 12952.46,3846.64 h30
  text "NC_DRILL FILES" at 13089.46,3846.64 h30
  text "PTH COPPER THICKNESS:" at 11403.23,3688.64 h30
  text "X" at 12533.46,3688.64 h30
  text "20-30 um" at 12670.46,3688.64 h30
  text "OTHER" at 13387.46,3688.64 h30
  text "BOARD FINISH:" at 11328.46,3529.64 h30
  text "SILKSCREEN:" at 11483.68,3411.64 h30
  text "X" at 12432.46,3411.64 h30
  text "TOP" at 12558.46,3411.64 h30
  text "X" at 12942.46,3411.64 h30
  text "BOTTOM" at 13069.46,3411.64 h30
  text "SILKSCREEN COLOR:" at 11483.68,3244.64 h30
  text "X" at 12431.42,3244.64 h30
  text "WHITE" at 12558.46,3244.64 h30
  text "OTHER" at 13069.46,3244.64 h30
  text "X" at 12562.42,3085.44 h30
  text "GREEN" at 12689.46,3085.44 h30
  text "OTHER" at 13307.46,3085.44 h30
  text "SOLDER RESIST COLOR:" at 11483.68,3074.64 h30
  text "X" at 12562.42,2915.44 h30
  text "MATTE" at 12689.46,2915.44 h30
  text "SEMI-GLOSS" at 13307,2914.8 h30
  text "IMMERSION GOLD (ENIG)" at 12389.46,2726.92 h30
  text "ENEPIG" at 13727,2723.64 h30
  text "SURFACE FINISH:" at 11328.46,2722.64 h30
  text "X" at 12202.51,2722.64 h30
  text "IMM. TIN/SILVER OR EQUIV" at 11658,2565.64 h30
  text "OTHER" at 13089.46,2565.64 h30
  text "ARRAY/PANEL:" at 11328.46,2386.64 h30
  text "CUT AND TRIM PER M1 BOARD OUTLINE" at 12389.46,2382.35 h30
  text "N.C. ROUTE" at 12389.46,2230.64 h30
  text "X" at 13068.46,2230.64 h30
  text "V. SCORE" at 13255.46,2230.64 h30
  text "CERTIFICATION:" at 11328.46,2093.64 h30
  text "MATERIALS AND WORKMANSHIP FOR ALL PCBS" at 12053.46,2093.64 h30
  text "TO MEET OR EXCEED THE REQUIREMENTS OF:" at 12053.46,1995.64 h30
  text "X" at 11679.96,1859.13 h30
  text "ANSI IPC-A-600F CLASS ->" at 11818.96,1859.13 h30
  text "X" at 13458.02,1859.13 h30
  text "2" at 13576.96,1859.14 h30
  text "1" at 13261.96,1857.64 h30
  text "3" at 13930.96,1857.64 h30
  text "X" at 12494.02,1699.64 h30
  text "RoHS" at 12630.96,1699.64 h30
  text "OTHER" at 13275.36,1699.64 h30
  text "PER ORDER" at 13672.42,1699.64 h30
  text "ALL BOARDS MUST MEET OR EXCEED UL94-V0 REQUIREMENTS." at 11356,1534 h30
  text "PCB MUST BEAR THE UL94V-0 UL REGISTERED MATERIAL ID NUMBER" at 11356,1414 h30
  text "ADDITIONAL REQUIREMENTS:" at 11328.46,1240.64 h30
  text "MICROSECTION:" at 11403.23,1125.64 h30
  text "YES" at 12308.96,1125.64 h30
  text "REQUIRED" at 13170.46,969.49 h30
  text "BARE BOARD ELEC. TEST:" at 11403.23,966.64 h30
  text "NONE" at 12708.96,966.64 h30
  text "X" at 13043.46,966.64 h30
  text "PER ORDER" at 13762.46,966.64 h30
  text ".Layer_Name" at 577,-858.49 h30
M11 Gerber Information:
  lines w10: -292,-930.17 6308,-930.17 ; -292,-726.83 6310,-726.83 ; -292,-523.5 -292,-1133.5 3713,-1133.5 6310,-1133.5 6310,-523.5 -291.5,-523.5 -291.5,-1133.5 1284,-1133.5 ; 2173,-1133.5 2173,-523.5 ; 3440,-726.83 3440,-523.5 ; 4280,-726.83 4280,-523.5 ; 4902,-1140 4902,-937.17
  text "ALL ARTWORK VIEWED FROM TOP SIDE" at -228.5,-655.67 h30
  text "BOARD #:" at 2248,-655.67 h30
  text ".PRJ_Number" at 2793.5,-655.67 h30
  text "REV:" at 3638,-655.67 h30
  text ".PCB_Rev" at 3929.5,-655.67 h30
  text "SVN REV:" at 4476,-655.67 h30
  text ".VersionControl_RevNumber" at 4982,-655.67 h30
  text "LAYER NAME =" at -228.5,-858.49 h30
  text "TID #:" at 2248,-859 h30
  text ".TID" at 2793.5,-859 h30
  text "PLOT NAME =" at -228.5,-1064.34 h30
  text ".plot_File_Name" at 577,-1064.34 h30
  text "GENERATED    :" at 2250,-1064.34 h30
  text ".Print_Date" at 3119.5,-1064.34 h30
  text ".Print_Time" at 3848.5,-1064.34 h30
  text "TEXAS INSTRUMENTS" at 5113,-1064.34 h30
M12 Stackup:
  drawing of 399 lines, arcs and shapes, not listed
  text "Layer" at 9778.08,7762.5 h30
  text "Name" at 9993.03,7762.5 h30
  text "Material" at 10472.9,7762.5 h30
  text "Thickness" at 10912.79,7762.5 h30
  text "Constant" at 11247.7,7762.5 h30
  text "Board Layer Stack" at 11542.63,7762.5 h30
  text "Top Overlay" at 9993.03,7702.5 h30
  text "Top Solder" at 9993.03,7642.5 h30
  text "Solder Resist" at 10472.9,7642.5 h30
  text "0.40mil" at 10912.79,7642.5 h30
  text "3.5" at 11247.7,7642.5 h30
  text "1" at 9778.08,7582.5 h30
  text "Top Layer" at 9993.03,7582.5 h30
  text "1.40mil" at 10912.79,7582.5 h30
  text "Dielectric 1" at 9993.03,7522.5 h30
  text "PP-006" at 10472.9,7522.5 h30
  text "2.80mil" at 10912.79,7522.5 h30
  text "4.1" at 11247.7,7522.5 h30
  text "2" at 9778.08,7462.5 h30
  text "Power / GND 1" at 9993.03,7462.5 h30
  text "CF-004" at 10472.9,7462.5 h30
  text "1.38mil" at 10912.79,7462.5 h30
  text "Dielectric 3" at 9993.03,7402.5 h30
  text "PP-006" at 10472.9,7402.5 h30
  text "2.80mil" at 10912.79,7402.5 h30
  text "4.1" at 11247.7,7402.5 h30
  text "3" at 9778.08,7342.5 h30
  text "Signal Layer 1" at 9993.03,7342.5 h30
  text "CF-004" at 10472.9,7342.5 h30
  text "1.38mil" at 10912.79,7342.5 h30
  text "Dielectric1" at 9993.03,7282.5 h30
  text "FR-4" at 10472.9,7282.5 h30
  text "59.20mil" at 10912.79,7282.5 h30
  text "4.8" at 11247.7,7282.5 h30
  text "4" at 9778.08,7222.5 h30
  text "Signal Layer 2" at 9993.03,7222.5 h30
  text "CF-004" at 10472.9,7222.5 h30
  text "1.38mil" at 10912.79,7222.5 h30
  text "Dielectric 4" at 9993.03,7162.5 h30
  text "PP-006" at 10472.9,7162.5 h30
  text "2.80mil" at 10912.79,7162.5 h30
  text "4.1" at 11247.7,7162.5 h30
  text "5" at 9778.08,7102.5 h30
  text "Power / GND 2" at 9993.03,7102.5 h30
  text "CF-004" at 10472.9,7102.5 h30
  text "1.38mil" at 10912.79,7102.5 h30
  text "Dielectric 2" at 9993.03,7042.5 h30
  text "PP-006" at 10472.9,7042.5 h30
  text "2.80mil" at 10912.79,7042.5 h30
  text "4.1" at 11247.7,7042.5 h30
  text "6" at 9778.08,6982.5 h30
  text "Bottom Layer" at 9993.03,6982.5 h30
  text "1.40mil" at 10912.79,6982.5 h30
  text "Bottom Solder" at 9993.03,6922.5 h30
  text "Solder Resist" at 10472.9,6922.5 h30
  text "0.40mil" at 10912.79,6922.5 h30
  text "3.5" at 11247.7,6922.5 h30
  text "Bottom Overlay" at 9993.03,6862.5 h30
  text ".Layer_Name" at 577,-858.49 h30
M13 Component Bodies Top:
  text ".Layer_Name" at 577,-858.49 h30
M14 Component Bodies Bottom:
  text ".Layer_Name" at 577,-858.49 h30
M15 Courtyards Top:
  text ".Layer_Name" at 577,-858.49 h30
M16 Courtyards Bottom:
  text ".Layer_Name" at 577,-858.49 h30
Drill Drawing:
  text ".Layer_Name" at 577,-858.49 h30

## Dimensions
0,0 to 6425,790 on M2 Board Dimensions
0,-400 to 1000,-400 on M2 Board Dimensions
5635,0 to 0,5322.16 on M2 Board Dimensions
